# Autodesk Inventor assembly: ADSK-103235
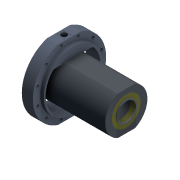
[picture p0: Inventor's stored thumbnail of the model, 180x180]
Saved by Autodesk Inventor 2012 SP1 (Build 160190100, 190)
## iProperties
Shininess: 0.0
Created: 2000-09
Part Number: ADSK-103235
Document SubType Name: Assembly
Designer: gao
Stock Number: ADSK-103235
Density: 0.0
Volumn: 0.0
Area: 0.0
PropertySet Name: Model Information
Control State: 0
Master: False
Checked Out: False
Author: gao
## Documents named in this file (6)
- D:\AOTC\Autodesk Inventor 2012 Essential for New Users\Autodesk Inventor 2012 Essentials - Project Files\Learning\Workspace\Sub-Assemblies\ADSK-103235.iam
- D:\AOTC\Autodesk Inventor 2012 Essential for New Users\Autodesk Inventor 2012 Essentials - Project Files\Learning\Workspace\Parts\ADSK-103430.ipt
- D:\AOTC\Autodesk Inventor 2012 Essential for New Users\Autodesk Inventor 2012 Essentials - Project Files\Learning\Workspace\Parts\ADSK-104023.ipt
- D:\AOTC\Autodesk Inventor 2012 Essential for New Users\Autodesk Inventor 2012 Essentials - Project Files\Learning\Workspace\Parts\ADSK-103429.ipt
- D:\AOTC\Autodesk Inventor 2012 Essential for New Users\Autodesk Inventor 2012 Essentials - Project Files\Learning\Workspace\Parts\ADSK-104024.ipt
- D:\AOTC\Autodesk Inventor 2012 Essential for New Users\Autodesk Inventor 2012 Essentials - Project Files\Learning\Workspace\Parts\ADSK-103957.ipt
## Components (5 placed, 5 different names)
1. ADSK-104023:1 — Insert:1, Insert:2, Angle:1, Mate:1, Mate:2, Angle:2
2. ADSK-103429:1 — Insert:2, Insert:3
3. ADSK-103430:1 — Insert:1
4. ADSK-104024:1 — Angle:1, Mate:1, Mate:2, Angle:2
5. ADSK-103957:1 — Insert:3
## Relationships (7: Insert 3, Angle 2, Mate 2)
- Insert:1: ADSK-104023:1 ↔ ADSK-103430:1
- Insert:2: ADSK-104023:1 ↔ ADSK-103429:1
- Angle:1: ADSK-104023:1 ↔ ADSK-104024:1
- Mate:1: ADSK-104023:1 ↔ ADSK-104024:1
- Insert:3: ADSK-103429:1 ↔ ADSK-103957:1
- Mate:2: ADSK-104023:1 ↔ ADSK-104024:1
- Angle:2: ADSK-104023:1 ↔ ADSK-104024:1
